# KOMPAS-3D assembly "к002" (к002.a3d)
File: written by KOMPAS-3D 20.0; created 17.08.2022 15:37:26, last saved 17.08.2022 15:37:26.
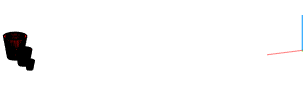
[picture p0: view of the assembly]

Document properties: Автор: artemsv220@gmail.com; Полное имя файла: \\192.168.2.25\новая общая папка\Медиа\Светильники\Кашпо\Кашпо и вазоны\DWG\к002.a3d

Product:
- Part/product: к002
  - Component [detail]: Cylinder129  | qty 6  | source file: \\192.168.2.25\новая общая папка\Медиа\Светильники\Кашпо\Кашпо и вазоны\DWG\Cylinder129_2.m3d
  - Component [detail]: Cylinder135  | qty 6  | source file: \\192.168.2.25\новая общая папка\Медиа\Светильники\Кашпо\Кашпо и вазоны\DWG\Cylinder135_1.m3d
  - Component [detail]: Cylinder141  | qty 6  | source file: \\192.168.2.25\новая общая папка\Медиа\Светильники\Кашпо\Кашпо и вазоны\DWG\Cylinder141.m3d

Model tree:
1. Операция без истории:1
2. Операция без истории:2
3. Операция без истории:3

Referenced files in \\192.168.2.25\новая общая папка\Медиа\Светильники\Кашпо\Кашпо и вазоны\DWG\: Cylinder141.m3d, Cylinder135_1.m3d, Cylinder129_2.m3d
